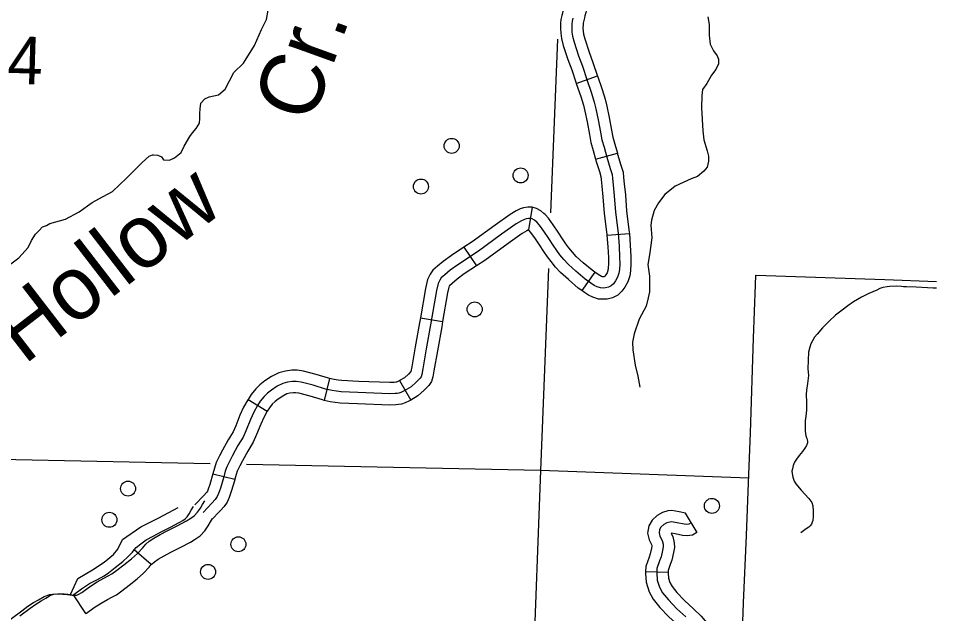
# Model space of a CAD drawing. Extents: x 653372 to 905732, y 627442 to 787275.
# Drawn here: x 722553 to 728673, y 755873 to 759842 of the extents above; entities that cross this region are included whole.
import ezdxf

# ---------------------------------------------------------------- set-up
doc = ezdxf.new("R2010")
doc.units = 0
for name, color, linetype in [('32', 7, 'Continuous'), ('35', 7, 'Continuous'), ('45', 7, 'Continuous'), ('5', 7, 'Continuous'), ('56', 7, 'Continuous'), ('6', 7, 'Continuous')]:
    doc.layers.add(name, color=color, linetype=linetype)

msp = doc.modelspace()

# ---------------------------------------------------------------- linework, layer by layer
at = {"layer": '32'}
for p, q in [((726270.3, 759408.8), (726412, 759458)), ((726400.1, 758903.1), (726544.8, 758942.7)), ((725976.9, 758582.9), (725953.1, 758431.9)), ((726475.5, 758396.6), (726625.1, 758408.4)), ((725522.8, 758316.5), (725605.4, 758191.3)), ((726394.1, 758150), (726307.2, 758027.8)), ((725232.6, 757846), (725380.5, 757820.7)), ((724626.3, 757441.4), (724591.6, 757295.5)), ((725092.9, 757426.9), (725168.8, 757297.5)), ((724083.5, 757301.7), (724211.5, 757223.4)), ((723849.7, 756804.5), (723995.5, 756769.1)), ((726997.3, 756543.2), (727074.9, 756414.9)), ((723438.7, 756200.4), (723325.5, 756298.8)), ((726733.4, 756153.5), (726883.3, 756149)), ((723002, 755873.5), (722919.7, 755998.9))]:
    msp.add_line(p, q, dxfattribs=at)
for points in [[(726203, 759965.3), (726198.6, 759952.2), (726190.2, 759923.3), (726181.2, 759892.7), (726178.3, 759876.5), (726174.3, 759860.1), (726169.3, 759834.4), (726166.6, 759811.8), (726165.5, 759773.7), (726167.2, 759742.7), (726171.7, 759707.1), (726184.7, 759662), (726215.7, 759567.8), (726240.7, 759499.2), (726270, 759409.4), (726270.3, 759408.5)], [(726345.2, 759917.6), (726341.8, 759907.5), (726334.2, 759881.2), (726327.4, 759858), (726325.1, 759845.7), (726320.9, 759828), (726317.6, 759811.1), (726316.4, 759800.8), (726315.6, 759775.6), (726316.7, 759756.4), (726319.1, 759737.5), (726328.1, 759706.2), (726357.4, 759617), (726382.5, 759548.2), (726412.1, 759457.5), (726411.9, 759458.2)], [(726247.6, 759844), (726243.4, 759822.7), (726241.5, 759806.3), (726240.5, 759774.6), (726241.9, 759749.6), (726245.4, 759722.3), (726256.4, 759684.1), (726286.5, 759592.4), (726311.6, 759523.7), (726341.1, 759433.4), (726372, 759344.4), (726390.9, 759283.8), (726401.7, 759239.2), (726416.7, 759166.5), (726432, 759082.4), (726441.3, 759032.8), (726456.2, 758982.3), (726474.2, 758916.4)], [(726412, 759458), (726443.2, 759367.9), (726463.2, 759303.8), (726474.9, 759255.6), (726490.3, 759180.8), (726505.8, 759096), (726514.3, 759050.3), (726528.3, 759002.8), (726544.8, 758942.7)], [(726270.3, 759408.8), (726300.8, 759321), (726318.6, 759263.8), (726328.5, 759222.8), (726343.1, 759152.2), (726358.3, 759068.8), (726368.2, 759015.3), (726384, 758961.8), (726400.1, 758903.1)], [(726544.8, 758942.6), (726546.2, 758937.3), (726568.7, 758864.1), (726583.2, 758816.6), (726586.7, 758782), (726591.2, 758738.9), (726598.4, 758665.4), (726606.4, 758556.9), (726624.4, 758417.1), (726625.1, 758408.4)], [(726474.2, 758916.4), (726497, 758842.1), (726509.4, 758801.7), (726512.1, 758774.4), (726516.5, 758731.4), (726523.7, 758659), (726531.8, 758549.4), (726549.7, 758409.4), (726556.5, 758324.1), (726560, 758251.1), (726560.8, 758206), (726558.9, 758167.5), (726554.6, 758144), (726545.9, 758116.1), (726532.3, 758091.5), (726518.2, 758072.6), (726503.5, 758058.8), (726486.8, 758050), (726465.2, 758044.9), (726450.2, 758043.9), (726432.3, 758044.5), (726410.4, 758051.6), (726390.7, 758062.2), (726368.2, 758076.4), (726330.4, 758103.3), (726268.4, 758156.6), (726218.3, 758201.7), (726188.5, 758233.4), (726162.4, 758266.3), (726141.1, 758294.9), (726117.8, 758329.9), (726087.7, 758374.4), (726055.6, 758422.5), (726026.1, 758463.5), (726010.9, 758481.1), (725992.1, 758497.4), (725978, 758504.9), (725965.9, 758508.2), (725953.1, 758508.5), (725937.3, 758506.2), (725926.5, 758502.2), (725906.2, 758492.8), (725870.5, 758471.7), (725773.7, 758402.4), (725619.6, 758290.5), (725481.8, 758199.5), (725431.3, 758162.5), (725395.4, 758132.1), (725371.2, 758111.4), (725360.8, 758097.4), (725350.1, 758075.5), (725339.7, 758027)], [(726400.1, 758903.1), (726402.2, 758895.5), (726425.3, 758820.1), (726435.5, 758786.8), (726437.5, 758766.8), (726441.9, 758723.9), (726448.9, 758652.5), (726457.2, 758541.8), (726475.1, 758401.7), (726475.5, 758396.7)], [(726055.8, 758541.3), (726034.9, 758559.5), (726005.8, 758575.1), (725976.9, 758582.9), (725948.6, 758583.7), (725918.6, 758579.2), (725897.8, 758571.6), (725871.2, 758559.3), (725829.5, 758534.6), (725729.9, 758463.2), (725576.9, 758352.2), (725522.8, 758316.5)], [(726394.1, 758150), (726376.7, 758162.4), (726318, 758212.9), (726270.8, 758255.4), (726245.3, 758282.5), (726221.8, 758312.1), (726202.4, 758338.1), (726180.1, 758371.6), (726150, 758416.2), (726117.2, 758465.3), (726085, 758510), (726064.1, 758534.2), (726055.8, 758541.3)], [(725957.6, 758428), (725953.1, 758431.9), (725941.1, 758426.3), (725911.5, 758408.8), (725817.6, 758341.6), (725662.3, 758228.8), (725605.4, 758191.3)], [(726307.2, 758027.8), (726284.2, 758044.2), (726218.9, 758100.3), (726165.8, 758148.1), (726131.8, 758184.3), (726102.9, 758220.6), (726079.7, 758251.6), (726055.5, 758288.1), (726025.5, 758332.6), (725993.9, 758379.8), (725967.1, 758416.9), (725957.6, 758428), (725957.6, 758428)], [(726625.1, 758408.4), (726631.3, 758328.9), (726635, 758253.6), (726635.8, 758204.9), (726633.6, 758158.9), (726627.6, 758126.1), (726615.3, 758086.5), (726595.5, 758050.7), (726574.3, 758022.5), (726547.5, 757997.2), (726513.2, 757979.2), (726476.3, 757970.5), (726451.5, 757968.9), (726419.4, 757969.8), (726380.8, 757982.3), (726352.7, 757997.4), (726326.4, 758014.2), (726307.2, 758027.8)], [(726475.5, 758396.6), (726481.6, 758319.4), (726485, 758248.6), (726485.8, 758207.2), (726484.3, 758176.1), (726481.7, 758162), (726476.6, 758145.7), (726469.2, 758132.3), (726462.1, 758122.8), (726459.8, 758120.7), (726454.1, 758119.3), (726448.8, 758119), (726445.2, 758119.1), (726439.9, 758120.8), (726428.6, 758126.9), (726410.1, 758138.7), (726394.1, 758150)], [(725522.8, 758316.5), (725438.9, 758261.1), (725384.9, 758221.4), (725346.8, 758189.2), (725316.1, 758162.9), (725296.5, 758136.6), (725278.7, 758100.2), (725266.1, 758041.2), (725232.6, 757846)], [(725605.4, 758191.3), (725524.7, 758138), (725477.8, 758103.5), (725444, 758075), (725426.3, 758059.8), (725425.1, 758058.2), (725421.5, 758050.9), (725413.4, 758012.8), (725380.5, 757820.7)], [(725339.7, 758027), (725300.7, 757799.4), (725271.6, 757638.7), (725248.3, 757504.6), (725241.5, 757468.3), (725237.4, 757452.7), (725230, 757442.2), (725204.9, 757416.5), (725170.4, 757385.4), (725124.5, 757358.5), (725102.1, 757348.5), (725088.3, 757343.2), (725077.6, 757342), (725063.2, 757340.3), (725028.2, 757339.2), (724815.6, 757347.1), (724704, 757352.5), (724674, 757355.6), (724644.2, 757360.1), (724599.5, 757370.7), (724516.6, 757396.1), (724437.9, 757415.6), (724405.2, 757421.6), (724380.1, 757420.9), (724347.1, 757416.9), (724316.1, 757408.5), (724277.7, 757388.9), (724239.1, 757364.4), (724213.4, 757343), (724190.7, 757320.8), (724164.8, 757290.8), (724146.8, 757261.3), (724121.1, 757215.6), (724098.9, 757167), (724071.1, 757097.1), (724050.4, 757050.7), (724016.5, 756993.8), (723979.5, 756928.5), (723961.3, 756892.5), (723941.5, 756853.1), (723931.3, 756822.7), (723922.4, 756785.8), (723900.1, 756711), (723887.6, 756674.9), (723878.4, 756653.7), (723864.9, 756634.1), (723842.8, 756609.8), (723783.7, 756547.9)], [(725232.6, 757846), (725226.9, 757812.4), (725197.8, 757651.8), (725174.5, 757517.9), (725168.6, 757486.7), (725152.9, 757470.6), (725125.8, 757446.2), (725092.9, 757426.9)], [(725380.5, 757820.7), (725374.6, 757786.4), (725345.4, 757625.6), (725322.1, 757491.2), (725314.7, 757452), (725306.6, 757420.5), (725287.7, 757394), (725256.9, 757362.4), (725214.9, 757324.5), (725168.8, 757297.5)], [(724626.3, 757441.4), (724619.1, 757443.1), (724536.6, 757468.4), (724453.6, 757488.9), (724411, 757496.8), (724374.6, 757495.8), (724332.7, 757490.7), (724289.1, 757478.9), (724240.4, 757454.1), (724194.7, 757425.1), (724163.1, 757398.7), (724136, 757372.2), (724104, 757335.2), (724083.5, 757301.7)], [(725092.9, 757426.9), (725090.2, 757425.3), (725073.2, 757417.7), (725070.7, 757416.7), (725069.3, 757416.6), (725057.6, 757415.2), (725028.4, 757414.3), (724818.8, 757422), (724709.6, 757427.4), (724683.4, 757430), (724658.4, 757433.8), (724626.3, 757441.4)], [(724591.6, 757295.5), (724579.8, 757298.3), (724496.6, 757323.8), (724422.1, 757342.2), (724399.4, 757346.4), (724385.7, 757346), (724361.5, 757343.1), (724343.2, 757338.1), (724314.9, 757323.7), (724283.4, 757303.7), (724263.7, 757287.3), (724245.4, 757269.4), (724225.6, 757246.4), (724211.5, 757223.4)], [(724083.5, 757301.7), (724082.1, 757299.3), (724054.2, 757249.6), (724029.9, 757196.4), (724002, 757126.3), (723983.7, 757085.3), (723951.7, 757031.5), (723913.4, 756963.9), (723894.3, 756926.3), (723872.1, 756882), (723859.2, 756843.5), (723849.7, 756804.5)], [(725168.8, 757297.5), (725158.9, 757291.7), (725130.9, 757279.2), (725106, 757269.6), (725085.9, 757267.5), (725068.9, 757265.5), (725028, 757264.2), (724812.4, 757272.1), (724698.3, 757277.7), (724664.7, 757281.2), (724629.9, 757286.4), (724591.6, 757295.5)], [(724211.5, 757223.4), (724211.5, 757223.4), (724188, 757181.6), (724167.9, 757137.5), (724140.2, 757068), (724117.1, 757016.1), (724081.4, 756956.2), (724045.6, 756893), (724028.3, 756858.8), (724011, 756824.2), (724003.5, 756801.8), (723995.5, 756769.1)], [(723849.9, 756805.3), (723828.7, 756734), (723817.7, 756702.2), (723812.5, 756690.2), (723806, 756680.8), (723787.9, 756660.9), (723729.5, 756599.7)], [(723995.5, 756769.1), (723994.8, 756766.2), (723971.5, 756688), (723957.5, 756647.6), (723944.3, 756617.2), (723923.9, 756587.5), (723897.6, 756558.6), (723838, 756496.1)], [(723498.5, 756401.2), (723545.2, 756426.5), (723612.1, 756459.5), (723673, 756491.6), (723701.4, 756508.9), (723725.5, 756526.3), (723747.3, 756549.3), (723765.7, 756576), (723779.7, 756601), (723794.6, 756624.8)], [(723325.5, 756298.8), (723338.9, 756314.1), (723369.4, 756339), (723405.1, 756364.4), (723451.6, 756390.2), (723499.9, 756416.2), (723567.2, 756449.5), (723625.1, 756480), (723648.9, 756494.6), (723665.1, 756506.2), (723678, 756519.9), (723691.1, 756538.8), (723704.3, 756562.4), (723720.1, 756587.6)], [(726999.1, 756544.3), (726957.5, 756552.9), (726909, 756560), (726881.6, 756558.6), (726846.8, 756548.1), (726810.1, 756528.8), (726776.4, 756497), (726754.1, 756459.6), (726746.2, 756410.7), (726756.3, 756364.6), (726772.8, 756333.8), (726774.5, 756326.3), (726774.6, 756323.6), (726772.5, 756308.9), (726763.7, 756272.4), (726756, 756249.7), (726734.4, 756187.8), (726733.4, 756153.5)], [(723438.7, 756200.4), (723443.7, 756206.1), (723460.3, 756219.7), (723485.1, 756237.3), (723523.6, 756258.6), (723568.8, 756283), (723635.4, 756315.9), (723699.2, 756349.5), (723732, 756369.6), (723764.1, 756392.8), (723794.9, 756425), (723818.5, 756459.4), (723833.4, 756485.9), (723847.3, 756508.2)], [(727036.1, 756479), (727020.4, 756469.5), (727008.5, 756468), (726990.4, 756469.5), (726944.4, 756479), (726905.5, 756484.8), (726894.6, 756484.2), (726875.4, 756478.4), (726854.1, 756467.2), (726835.4, 756449.6), (726825.9, 756433.5), (726822.5, 756412.8), (726827.3, 756390.8), (726843.7, 756360.3), (726849.3, 756335.7), (726849.7, 756319.3), (726846.2, 756294.9), (726835.9, 756251.6), (726826.9, 756225.2), (726809, 756174), (726808, 756142.2), (726810.3, 756096.7), (726826.2, 756049.9), (726846.8, 756012.1), (726885.3, 755964.6), (726940.8, 755906.6), (727000.9, 755852.1)], [(722563.6, 755858), (722631.1, 755909.8), (722668.8, 755937.1), (722704, 755959.7), (722735.8, 755977.2), (722767.9, 755996.8), (722789.2, 756003.4), (722813.5, 756006.3), (722858.3, 756005.6), (722883, 756004.2), (722910.1, 755999.2), (722925.8, 755996.9), (722933, 755996.1), (722941.5, 755997), (722956.8, 756003.2), (722975.3, 756015.4), (723026.7, 756053.2), (723077, 756085.6), (723122.5, 756110.2), (723152, 756125.1), (723176, 756138.9), (723208.8, 756163.3), (723255.8, 756199.4), (723307.3, 756239.9), (723345.8, 756274.5), (723379.6, 756311), (723402.2, 756336.9), (723425.7, 756356.2), (723456, 756377.7), (723498.5, 756401.2)], [(727074.9, 756414.9), (727045.5, 756397), (727010.1, 756392.7), (726979.7, 756395.1), (726931.3, 756405.2), (726905.1, 756409), (726903.9, 756408.6), (726903.1, 756408.2), (726914.5, 756386.9), (726924.1, 756345), (726924.8, 756315), (726920, 756280.8), (726908, 756230.7), (726897.8, 756200.8), (726883.6, 756160.2), (726883.3, 756149)], [(722919.7, 755998.8), (722921.6, 756000.1), (722973.2, 756038.1), (723027.9, 756073.3), (723076.9, 756099.8), (723105.5, 756114.3), (723123.9, 756124.8), (723152.7, 756146.3), (723198.9, 756181.8), (723248.1, 756220.5), (723282.3, 756251.1), (723312.9, 756284.2), (723325.5, 756298.8)], [(723002, 755873.5), (723007.3, 755876.9), (723058.4, 755914.5), (723104.3, 755944.1), (723146.3, 755966.9), (723176.7, 755982.2), (723206.3, 755999.2), (723243.1, 756026.6), (723291, 756063.3), (723344.7, 756105.6), (723387.6, 756144.1), (723424.6, 756184.1), (723438.7, 756200.4)], [(726733.4, 756153.5), (726733, 756141.5), (726735.9, 756082.6), (726757.2, 756019.7), (726784.3, 755970.1), (726829, 755915), (726888.5, 755852.8), (726949.4, 755797.6), (726994.5, 755753.1), (727041.9, 755697.7), (727044.3, 755694)], [(726883.3, 756149), (726883.1, 756143), (726884.7, 756110.9), (726895.1, 756080.1), (726909.4, 756054), (726941.7, 756014.2), (726993.2, 755960.4), (727052.5, 755906.6), (727104.4, 755855.5), (727162.2, 755787.8), (727170, 755776)], [(722451.3, 755799.4), (722507.6, 755841), (722575.4, 755893.1), (722615.7, 755922.3), (722654.8, 755947.3), (722687.3, 755965.2), (722725.8, 755988.8), (722762.7, 756000.2), (722798.8, 756004.5), (722850.1, 756003.7), (722881.1, 756002), (722911.5, 755996.3), (722915.1, 755995.8), (722919.7, 755998.9)]]:
    msp.add_lwpolyline(points, dxfattribs=at)
at = {"layer": '35'}
for points in [[(722485.2, 758193.3), (722557, 758246.6), (722617.8, 758313.4), (722640.4, 758360.1), (722667.9, 758403.3), (722691.5, 758428.8), (722713.4, 758452.6), (722739.8, 758461.7), (722763, 758474.1), (722866.7, 758503.6), (722958, 758551.5), (723044.7, 758614.2), (723089.6, 758638.9), (723180.8, 758688.5), (723274.1, 758777.5), (723378.5, 758882.1), (723424.6, 758922.8), (723446.1, 758932), (723452.6, 758931.8), (723481.9, 758930.9), (723506.1, 758918.7), (723520, 758898.4), (723560.8, 758897.2), (723594, 758911.2), (723637.5, 758947.5), (723658.4, 758989.2), (723696.3, 759055.5), (723713.3, 759077.8), (723737, 759108.1), (723760.9, 759143.3), (723761.9, 759174.3), (723762.8, 759206.8), (723763.8, 759237.8), (723769.8, 759276.8), (723795.2, 759304.9), (723825, 759318.7), (723887.4, 759332.6), (723931, 759369.6), (723989.8, 759482.2), (724053.7, 759542.3), (724125.8, 759661), (724173.1, 759767.1), (724206.1, 759834.7), (724217.8, 759896.4)], [(727147.3, 759852.6), (727157.1, 759802), (727157.5, 759729.1), (727163.2, 759669.9), (727185.7, 759625.2), (727209.9, 759591.8), (727218, 759570.6), (727218.3, 759539.1), (727202.1, 759501.9), (727173.3, 759462.6), (727140.3, 759408.3), (727111.5, 759368.9), (727109, 759328.8), (727106.5, 759245.9), (727114.5, 759093.3), (727120.2, 759031.5), (727143.1, 758959.2), (727152.1, 758922.5), (727152.4, 758891.1), (727142.4, 758851.1), (727120.2, 758822.9), (727078.9, 758787.7), (727037, 758771.3), (726931.2, 758723), (726861.7, 758667.3), (726818.6, 758612), (726790.7, 758561.3), (726772.4, 758496.5), (726767.6, 758464), (726773.9, 758378.3)], [(726773.9, 758378.3), (726759.2, 758265.8), (726748.4, 758200.8), (726758.7, 758123.5), (726759.5, 758068.1), (726758.1, 758019.1), (726750.6, 757979.2), (726736.4, 757924.3), (726689.7, 757836.4), (726657.9, 757739.4), (726646.2, 757684.4), (726647.2, 757632.8), (726663, 757530.6), (726682.1, 757455.8), (726693.7, 757383)], [(722899.9, 756001), (722948.2, 756107.7), (723047.4, 756165.1), (723125.5, 756216.1), (723187.4, 756267.7), (723216.3, 756304), (723246.1, 756366.9), (723369.3, 756451.4), (723488, 756511.3), (723617.7, 756580.7)]]:
    msp.add_lwpolyline(points, dxfattribs=at)
at = {"layer": '45'}
msp.add_lwpolyline([(728672.8, 758042.9), (728650.5, 758043.7), (728537, 758049.9), (728471.7, 758053), (728461.1, 758053.3), (728451.5, 758051.9), (728438.4, 758053.7), (728408.3, 758055.7), (728361.1, 758054.6), (728342, 758052.4), (728313.3, 758047.1), (728294.6, 758040.4), (728273.6, 758030.9), (728220.8, 758007.9), (728171.3, 757983), (728118.3, 757951.6), (728080.6, 757925.8), (728042.1, 757896.1), (727999.7, 757863.8), (727956.5, 757822.5), (727912.6, 757779), (727876, 757736.4), (727858.6, 757716.7), (727844.5, 757693.1), (727834.9, 757673.2), (727827.5, 757649.9), (727819.8, 757617.3), (727816.5, 757564.2), (727815.3, 757504.9), (727817.9, 757461.6), (727811.3, 757408.7), (727805.5, 757364), (727803.5, 757335.5), (727805.3, 757284), (727806.6, 757252.1), (727805.9, 757229.7), (727800.8, 757190.9), (727796.5, 757158.6), (727797.7, 757122.1), (727797.2, 757089.6), (727800.2, 757059.3), (727807, 757040.6), (727810.1, 757032.7), (727812.1, 757023.6), (727811.7, 757013), (727805, 756994.2), (727794.4, 756976.5), (727778, 756954.1), (727757.7, 756928.3), (727738.5, 756903.4), (727726.1, 756882.5), (727716.5, 756860.9), (727712.5, 756839.2), (727708.7, 756824.1), (727709.3, 756806.8), (727713.6, 756784.2), (727722.9, 756756.5), (727734.1, 756738.2), (727770.9, 756695.7), (727820.8, 756641), (727841.3, 756615.5), (727846.8, 756592.9), (727850.8, 756558.6), (727850.8, 756521.1), (727847.7, 756493.7), (727844, 756482.6), (727839.2, 756469.9), (727829.9, 756458.4), (727821.2, 756450.3), (727804, 756437.9), (727766.9, 756412.1)], dxfattribs=at)
at = {"layer": '5'}
for points in [[(726146, 759702.8), (726100.3, 758545.6)], [(726085.6, 758174.8), (726032.3, 756827.2)], [(723830.8, 756872.1), (721672.9, 756916.1)], [(726032.3, 756827.2), (724073.5, 756867.1)], [(726032.3, 756827.2), (725982.5, 755462.5)], [(727420.5, 756776), (726032.3, 756827.2)]]:
    msp.add_lwpolyline(points, dxfattribs=at)
at = {"layer": '56'}
for centre in [(725440.7, 758991.9), (725900.1, 758794.8), (725235.9, 758720.8), (725593.9, 757901.8), (723283.8, 756706.9), (727175, 756591.7), (723159.5, 756499), (724019.1, 756335.9), (723817.1, 756151.8)]:
    msp.add_circle(centre, 50, dxfattribs=at)
at = {"layer": '6'}
msp.add_lwpolyline([(727371.5, 755568.7), (727386.6, 755944.7), (727404.9, 756395.1), (727418.9, 756744.7), (727431.2, 757079.5), (727452.7, 757710.3), (727464.8, 758065.9), (727467, 758130.8), (728328.6, 758100.5), (728672.8, 758088.4)], dxfattribs=at)

# ---------------------------------------------------------------- texts
at = {"layer": '35'}
for s, rotation, p in [('Cr.', 70.18408, (724506.5, 759129.3)), ('Hollow', 37.64356, (722591, 757527.6))]:
    msp.add_text(s, height=422.4, rotation=rotation, dxfattribs=at).set_placement(p)
at = {"layer": '56'}
msp.add_text('4', height=316.8, rotation=358.28003, dxfattribs=at).set_placement((722476.7, 759407.4))

doc.saveas('drawing.dxf')
